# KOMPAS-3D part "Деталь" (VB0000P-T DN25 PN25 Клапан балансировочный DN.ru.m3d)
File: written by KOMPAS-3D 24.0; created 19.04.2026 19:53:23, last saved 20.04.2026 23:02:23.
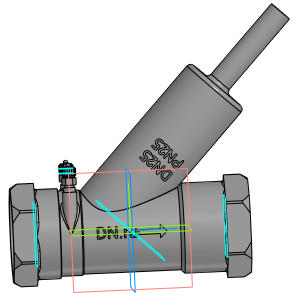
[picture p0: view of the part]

Document properties: Автор: mrdid; Полное имя файла: C:\Работа\VB0000P-T DN X PN 25 Клапан балансировочный DN.ru\DN25\исходные материалы\VB0000P-T DN25 PN25 Клапан балансировочный DN.ru.m3d

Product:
- Body: Тело 1  | qty 1
    Масса: 0.693362
- Body: Тело 2  | qty 1
    Масса: 0.693362
- Body: Тело 3  | qty 1
    Масса: 0.693362
- Body: Тело 4  | qty 1
    Масса: 0.693362
- Part/product: Деталь
    Масса: 0.00084
    Раздел спецификации: Прочие изделия
    Примечание: D080-01177

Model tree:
1. Эскиз:1
2. Элемент вращения:1
     Угол 1 = 360
3. Фаска:1  (with: Ребро.Элемент вращения:1)
     Угол = 45; Длина 1 = 3; Длина 2 = 3
4. Фаска:2  (with: Ребро.Элемент вращения:1)
     Угол = 45; Длина 1 = 2; Длина 2 = 2
5. Фаска:3  (with: Ребро.Элемент вращения:1)
     Угол = 45; Длина 1 = 1; Длина 2 = 1
6. Фаска:4  (with: Ребро.Элемент вращения:1)
     Угол = 30; Длина 1 = 3; Длина 2 = 1.73205
7. Смещенная плоскость:1  (with: Грань.Элемент вращения:1)
     Расстояние = 10
8. Эскиз:2
9. Элемент выдавливания:1  (with: Грань.Фаска:4)
     Расстояние 1 = 44.4556
10. Эскиз:3
11. Элемент выдавливания:2  (with: Грань.Фаска:4)
     Расстояние 2 = 20.7531
12. Смещенная плоскость:2  (with: Грань.Элемент вращения:1)
     Расстояние = 10
13. Эскиз:4  (with: Ребро.Фаска:4)
14. Элемент выдавливания:3  (with: Грань.Фаска:4)
     Расстояние 2 = 44.4556
15. Эскиз:5
16. Элемент выдавливания:4  (with: Грань.Фаска:4)
     Расстояние 2 = 54.4556
17. Фаска:5  (with: Ребро.Элемент выдавливания:4)
     Угол = 45; Длина 1 = 2; Длина 2 = 2
18. Плоскость под углом:1
     Угол = 43
19. Касательная плоскость:1  (with: Грань.Элемент вращения:1)
20. Эскиз:6  (with: Ребро.Фаска:3)
21. Элемент выдавливания:5  (with: Грань.Элемент вращения:1)
     Расстояние 1 = -10.0708; Смещение 1 = -2; Расстояние 2 = 70
22. Эскиз:7  (with: Грань.Элемент вращения:1)
23. Элемент выдавливания:6  (with: Грань.Элемент вращения:1)
24. Эскиз:8  (with: Грань.Элемент выдавливания:6, Ребро.Элемент выдавливания:6)
25. Элемент выдавливания:7
     Расстояние 1 = 2
26. Эскиз:9  (with: Грань.Элемент выдавливания:7, Ребро.Элемент выдавливания:7)
27. Элемент выдавливания:8
     Расстояние 1 = 1
28. Эскиз:10  (with: Грань.Элемент выдавливания:8, Ребро.Элемент выдавливания:6)
29. Элемент выдавливания:10
     Расстояние 1 = 3
30. Эскиз:11  (with: Грань.Элемент выдавливания:10, Ребро.Элемент выдавливания:6)
31. Элемент выдавливания:11
     Расстояние 1 = 1
32. Эскиз:12  (with: Грань.Элемент выдавливания:11, Ребро.Элемент выдавливания:6)
33. Элемент выдавливания:12
     Расстояние 1 = 3
34. Эскиз:13  (with: Грань.Элемент выдавливания:12, Ребро.Элемент выдавливания:7)
35. Элемент выдавливания:13
     Расстояние 1 = 2
36. Скругление:1  (with: Ребро.Элемент выдавливания:13)
     Радиус = 1
37. Средняя плоскость:2  (with: Грань.Элемент выдавливания:12, Грань.Элемент выдавливания:10)
38. Эскиз:14  (with: Ребро.Элемент выдавливания:11)
39. Элемент выдавливания:14
     Расстояние 1 = 0.5
40. Средняя плоскость:3  (with: Грань.Элемент выдавливания:12)
41. Эскиз:15  (with: Вершина.Элемент выдавливания:14, Ребро.Элемент выдавливания:14)
42. Эскиз:16  (with: Грань.Элемент выдавливания:12, Ребро.Скругление:1)
43. Элемент выдавливания:15
     Расстояние 1 = 0.5
44. Элемент выдавливания:16  (with: Грань.Элемент выдавливания:15, Грань.Элемент выдавливания:14)
     Расстояние 1 = 1.5; Расстояние 2 = 1.75
45. Скругление:2  (with: Ребро.Элемент выдавливания:14, Ребро.Элемент выдавливания:15, Ребро.Элемент выдавливания:16)
     Радиус = 1
46. Зеркальный массив:1
47. Экземпляр ( 1 )
48. Экземпляр ( 2 )  (with: Элемент выдавливания:15, Элемент выдавливания:16, Элемент выдавливания:14, Скругление:2)
49. Скругление:3  (with: Ребро.Элемент выдавливания:5)
     Радиус = 0.1
50. Скругление:4  (with: Ребро.Элемент выдавливания:6)
     Радиус = 1
51. Эскиз:17  (with: Грань.Элемент выдавливания:5, Ребро.Элемент выдавливания:5)
52. Элемент выдавливания:17
     Расстояние 1 = 41
53. Скругление:5  (with: Ребро.Элемент выдавливания:17, Ребро.Элемент выдавливания:5)
     Радиус = 2
54. Скругление:6  (with: Ребро.Элемент выдавливания:2, Ребро.Элемент выдавливания:4)
     Радиус = 1
55. Эскиз:19  (with: Грань.Элемент выдавливания:5)
56. Элемент выдавливания:19  (with: Грань.Элемент выдавливания:5)
     Расстояние 1 = 14.9627; Смещение 1 = 0.2
57. Эскиз:20
58. Элемент выдавливания:20  (with: Грань.Элемент вращения:1)
     Расстояние 1 = 17.7; Смещение 1 = 0.2; Расстояние 2 = 17.7; Смещение 2 = 0.2
59. Эскиз:21
60. Элемент выдавливания:21  (with: Грань.Элемент вращения:1)
     Расстояние 1 = 17.6988; Смещение 1 = 0.2
61. Эскиз:22  (with: Ребро.Фаска:2)
62. Элемент выдавливания:22
     Расстояние 1 = 50; Расстояние 2 = 70.6352

Expressions: 1/2*25.4
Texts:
  Линейный размер с обрывом
  GOST 26.020 Pr3
  var3D
  Dn+1
  Ds-1
  Ds-2
  Ds-4
  Gn+S+5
